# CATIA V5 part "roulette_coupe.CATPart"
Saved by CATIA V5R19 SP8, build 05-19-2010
Part number: roulette_coupe
Publications: "rayon_axe_roulette coupe"
Bounding box of the stored display mesh (mm): x -4.9 to 4.9, y -3.931 to 3.931, z -3.967 to 3.967
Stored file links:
  G:\EU_thinkMotion\CFAO_2010\MMS_groupe3\MMS_groupe3\A reprendre\ftixier\florent-tixier\florent-tixier\roulette_coupe.CATPart
  C:\Users\Azote\Desktop\CFAO\coupe_tube1.CATProduct
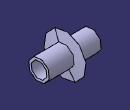
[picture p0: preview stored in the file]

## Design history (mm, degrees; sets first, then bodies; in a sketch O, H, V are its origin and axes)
Parameters
  `rayon_axe_roulette coupe` = 1.5 mm
External parameters (linked from other documents)
  External.R9 = 4 mm
Set1
  Line1 "suport_axe_rouleau": linked copy from another document
  Point1 "centre_roulette_coupe": linked copy from another document
Body1 (main body)
  Sketch1 on zx-plane, origin (0, 0, 0), H (-1, 0, 0), V (0, 0, 1)
    line L1 (-4.9, -1.5) -> (4.9, -1.5)
    line L2 (4.9, -1.5) -> (4.9, -2)
    line L3 (4.9, -2) -> (0.2102, -2)
    line L4 (0.2102, -2) -> (0, -4)
    point P5 (0, -4)
    line L5 (0, -4) -> (-0.2102, -2)
    point P6 (-0.2102, -2)
    line L6 (-0.2102, -2) -> (-4.9, -2)
    line L7 (-4.9, -2) -> (-4.9, -1.5)
    angle L4 L5 = 12
    angle L5 V = 6
    length L1 = 9.8
    length L2 = 0.5
    distance H P5 = 4 {= External.R9}
    distance L2 V = 4.9
    distance L1 H = 1.5 {= `rayon_axe_roulette coupe`}
    horizontal: L1 H, L3 H, L6 H
    vertical: L2 V, L7 V
    coincidence: P5 V, P6 L3
  Line2: type Angle, RefPoint Point1, Curve Line1, Support xy-plane, Start 0, End 20, Angle 90
  Shaft1: profile Sketch1, axis Line2, angle 360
